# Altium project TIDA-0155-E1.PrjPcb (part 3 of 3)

## Sheet Page6.SchDoc
size 431 x 279 mm; Date: Not shown in title block; ApprovedBy: Not shown in title block; CheckedBy: Not shown in title block; Author: Not shown in title block; CompanyName: Not shown in title block; Engineer: Not shown in title block; Organization: Not shown in title block; Address1: Not shown in title block; Address2: Not shown in title block; Address3: Not shown in title block; Address4: Not shown in title block; DocumentNumber: 1; Revision: Use project parameter SCH_Rev; SheetNumber: 2; SheetTotal: 3; PageSetup: Record=PageOptions¦CenterHorizontal=True¦CenterVertical=True¦PrintScale=1.00¦XCorrection=1.00¦YCorrection=1.00¦PrintKind=0¦BorderSize=5000000¦LeftOffset=0¦BottomOffset=0¦Orientation=2¦PaperLength=1000¦PaperWidth=1000¦Scale=100¦PaperSource=15¦PrintQuality=600¦MediaType=1¦DitherType=10¦PaperKind=Letter¦PrintScaleMode=1
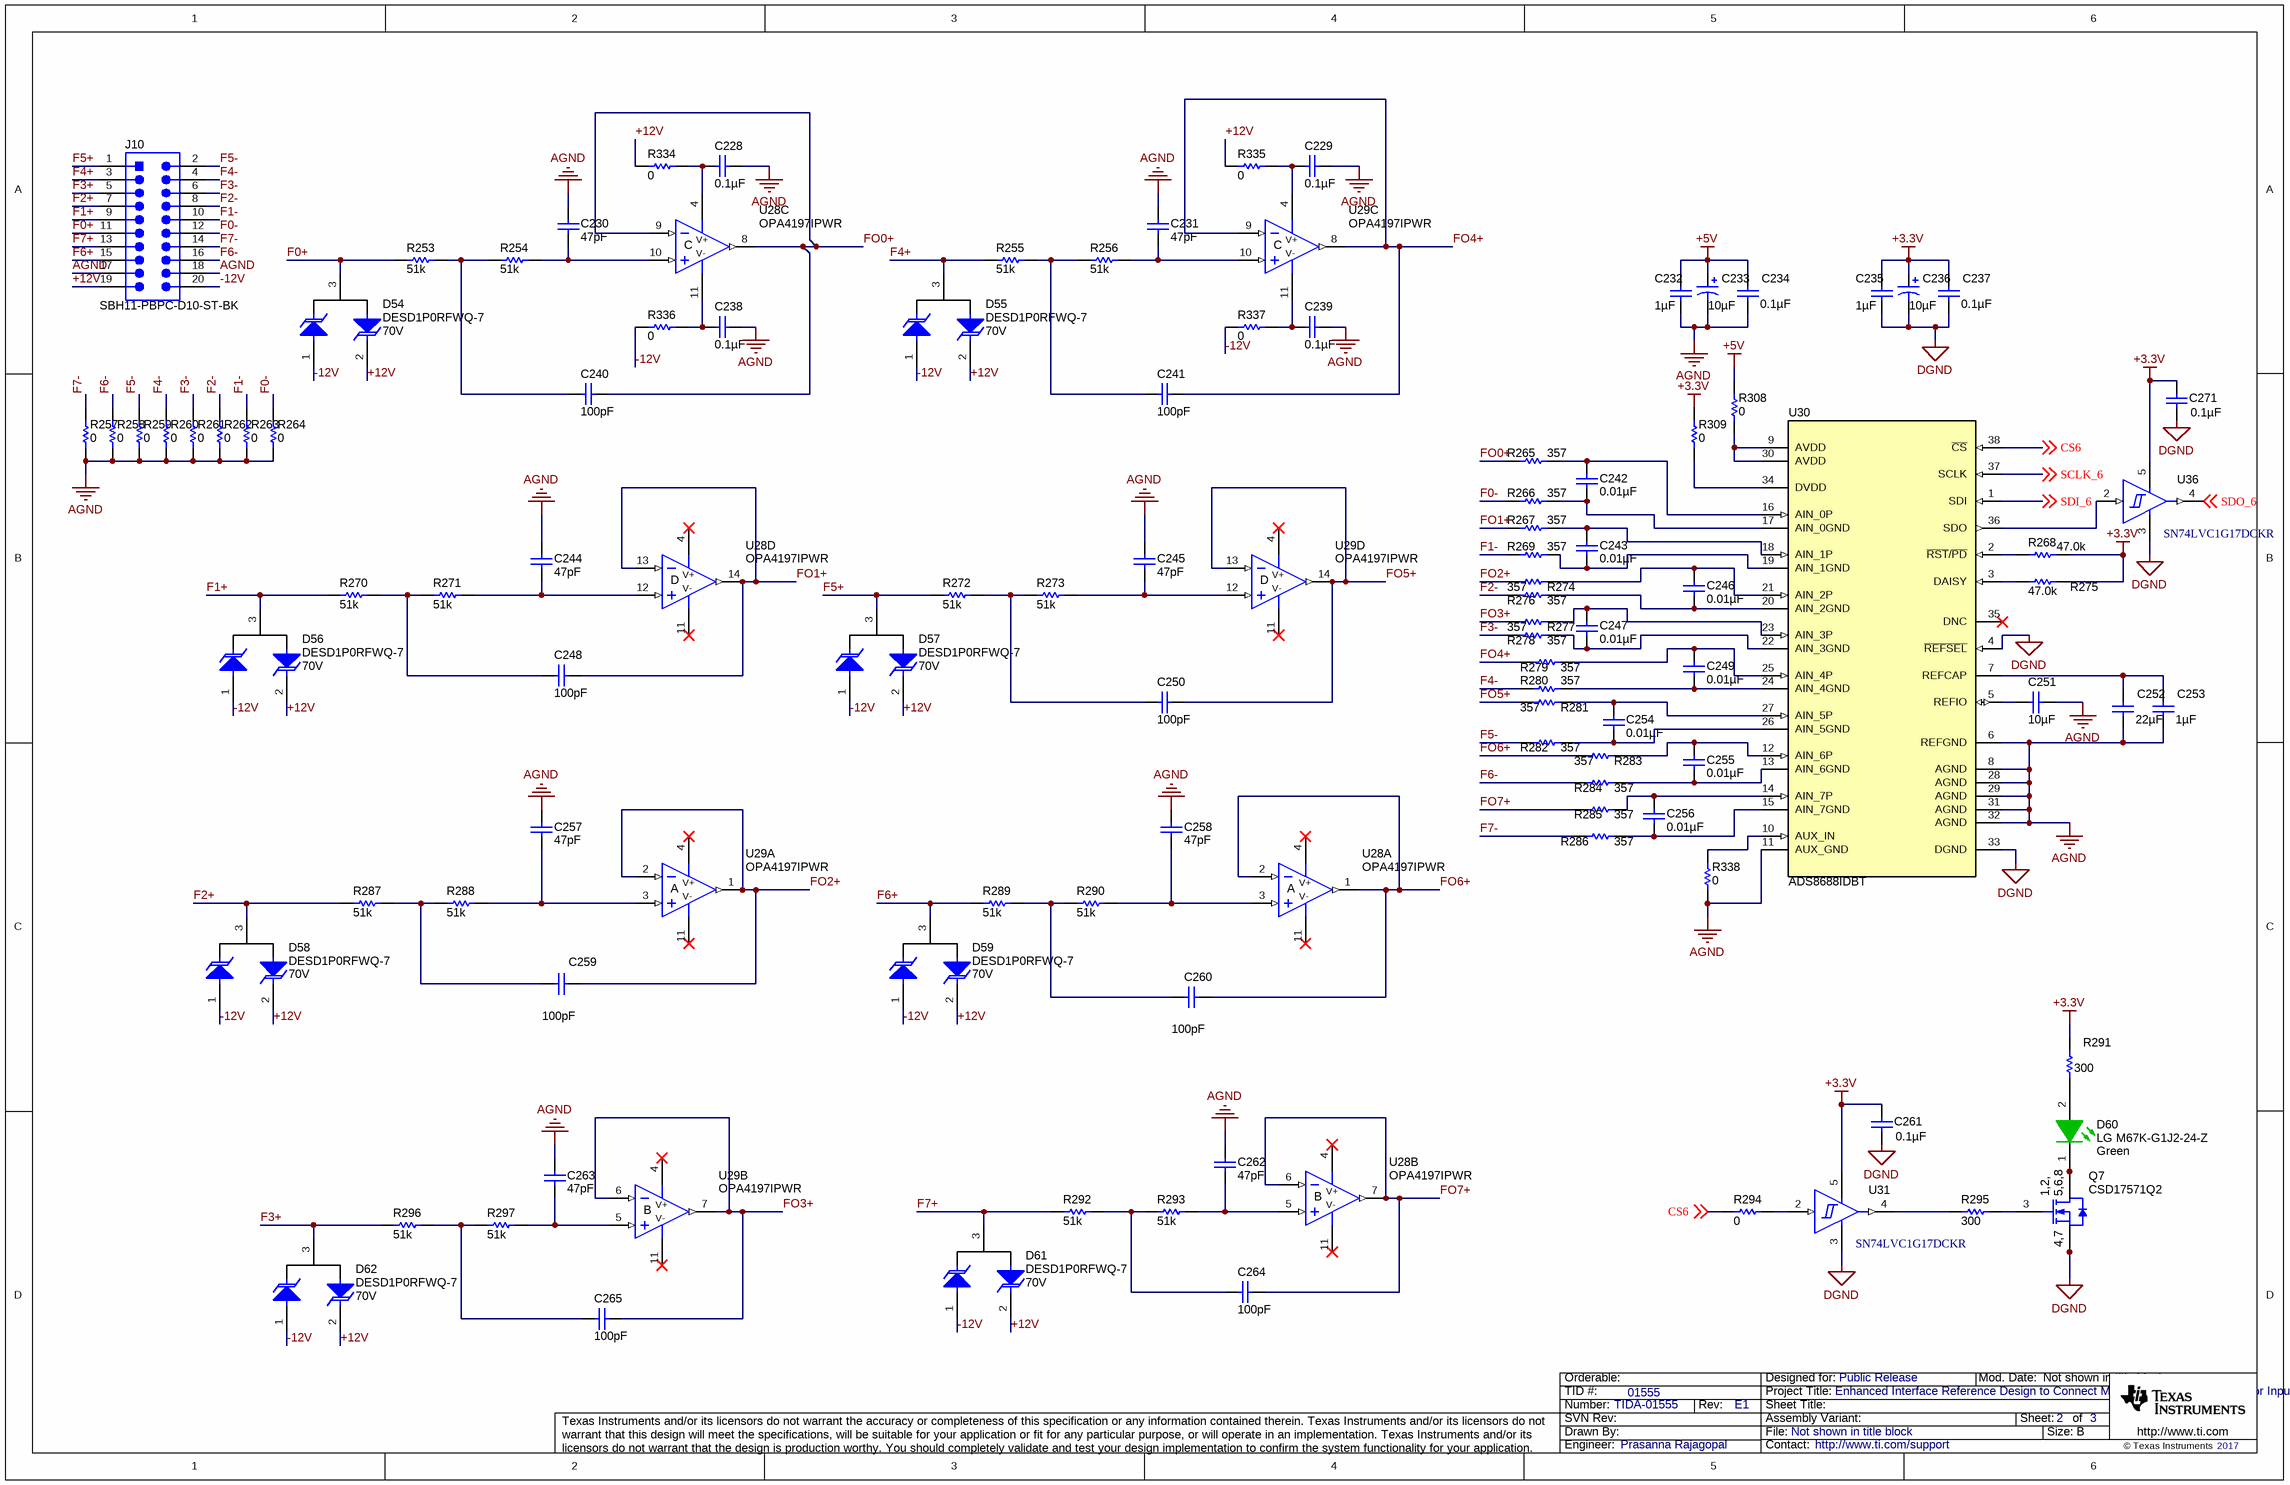
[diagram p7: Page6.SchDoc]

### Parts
C228  ValueDisplayed: 0.1µF  [0603]  (hidden comment: 06035C104KAT2A)
C229  ValueDisplayed: 0.1µF  [0603]  (hidden comment: 06035C104KAT2A)
C230  ValueDisplayed: 47pF  [0603]  (hidden comment: C0603C470J5GACTU)
C231  ValueDisplayed: 47pF  [0603]  (hidden comment: C0603C470J5GACTU)
C232  ValueDisplayed: 1µF  [0805_HV]  (hidden comment: LMK212B7105KD-T)
C233  ValueDisplayed: 10µF  [3216-18]  (hidden comment: TAJA106M010RNJ)
C234  ValueDisplayed: 0.1µF  [0402]  (hidden comment: C1005X5R1A104K050BA)
C235  ValueDisplayed: 1µF  [0805_HV]  (hidden comment: LMK212B7105KD-T)
C236  ValueDisplayed: 10µF  [3216-18]  (hidden comment: TAJA106M010RNJ)
C237  ValueDisplayed: 0.1µF  [0402]  (hidden comment: C1005X5R1A104K050BA)
C238  ValueDisplayed: 0.1µF  [0603]  (hidden comment: 06035C104KAT2A)
C239  ValueDisplayed: 0.1µF  [0603]  (hidden comment: 06035C104KAT2A)
C240  ValueDisplayed: 100pF  [0603]  (hidden comment: 06035A101FAT2A)
C241  ValueDisplayed: 100pF  [0603]  (hidden comment: 06035A101FAT2A)
C242  ValueDisplayed: 0.01µF  [0603]  (hidden comment: C1608X7R1H103K080AA)
C243  ValueDisplayed: 0.01µF  [0603]  (hidden comment: C1608X7R1H103K080AA)
C244  ValueDisplayed: 47pF  [0603]  (hidden comment: C0603C470J5GACTU)
C245  ValueDisplayed: 47pF  [0603]  (hidden comment: C0603C470J5GACTU)
C246  ValueDisplayed: 0.01µF  [0603]  (hidden comment: C1608X7R1H103K080AA)
C247  ValueDisplayed: 0.01µF  [0603]  (hidden comment: C1608X7R1H103K080AA)
C248  ValueDisplayed: 100pF  [0603]  (hidden comment: 06035A101FAT2A)
C249  ValueDisplayed: 0.01µF  [0603]  (hidden comment: C1608X7R1H103K080AA)
C250  ValueDisplayed: 100pF  [0603]  (hidden comment: 06035A101FAT2A)
C251  ValueDisplayed: 10µF  [0805_HV]  (hidden comment: GRM21BR71A106KE51L)
C252  ValueDisplayed: 22µF  [1210_280]  (hidden comment: C3225X7R1C226K250AC)
C253  ValueDisplayed: 1µF  [0603]  (hidden comment: C1608X7R1C105K080AC)
C254  ValueDisplayed: 0.01µF  [0603]  (hidden comment: C1608X7R1H103K080AA)
C255  ValueDisplayed: 0.01µF  [0603]  (hidden comment: C1608X7R1H103K080AA)
C256  ValueDisplayed: 0.01µF  [0603]  (hidden comment: C1608X7R1H103K080AA)
C257  ValueDisplayed: 47pF  [0603]  (hidden comment: C0603C470J5GACTU)
C258  ValueDisplayed: 47pF  [0603]  (hidden comment: C0603C470J5GACTU)
C259  ValueDisplayed: 100pF  [0603]  (hidden comment: 06035A101FAT2A)
C260  ValueDisplayed: 100pF  [0603]  (hidden comment: 06035A101FAT2A)
C261  ValueDisplayed: 0.1µF  [0603]  (hidden comment: GRM188R71C104KA01D)
C262  ValueDisplayed: 47pF  [0603]  (hidden comment: C0603C470J5GACTU)
C263  ValueDisplayed: 47pF  [0603]  (hidden comment: C0603C470J5GACTU)
C264  ValueDisplayed: 100pF  [0603]  (hidden comment: 06035A101FAT2A)
C265  ValueDisplayed: 100pF  [0603]  (hidden comment: 06035A101FAT2A)
C271  ValueDisplayed: 0.1µF  [0603]  (hidden comment: GRM188R71C104KA01D)
D54  DESD1P0RFWQ-7  value 70V  [SOT-323]
D55  DESD1P0RFWQ-7  value 70V  [SOT-323]
D56  DESD1P0RFWQ-7  value 70V  [SOT-323]
D57  DESD1P0RFWQ-7  value 70V  [SOT-323]
D58  DESD1P0RFWQ-7  value 70V  [SOT-323]
D59  DESD1P0RFWQ-7  value 70V  [SOT-323]
D60  LG M67K-G1J2-24-Z  value Green  [LG_M67K_Green]
D61  DESD1P0RFWQ-7  value 70V  [SOT-323]
D62  DESD1P0RFWQ-7  value 70V  [SOT-323]
J10  SBH11-PBPC-D10-ST-BK  [Sullins_SBH11-xxxC-D10-ST]
Q7  CSD17571Q2  [DQK0006C]
R253  ValueDisplayed: 51k  [0603]  (hidden comment: CRCW060351K0JNEA)
R254  ValueDisplayed: 51k  [0603]  (hidden comment: CRCW060351K0JNEA)
R255  ValueDisplayed: 51k  [0603]  (hidden comment: CRCW060351K0JNEA)
R256  ValueDisplayed: 51k  [0603]  (hidden comment: CRCW060351K0JNEA)
R257  ValueDisplayed: 0  [0603]  (hidden comment: CRCW06030000Z0EA)
R258  ValueDisplayed: 0  [0603]  (hidden comment: CRCW06030000Z0EA)
R259  ValueDisplayed: 0  [0603]  (hidden comment: CRCW06030000Z0EA)
R260  ValueDisplayed: 0  [0603]  (hidden comment: CRCW06030000Z0EA)
R261  ValueDisplayed: 0  [0603]  (hidden comment: CRCW06030000Z0EA)
R262  ValueDisplayed: 0  [0603]  (hidden comment: CRCW06030000Z0EA)
R263  ValueDisplayed: 0  [0603]  (hidden comment: CRCW06030000Z0EA)
R264  ValueDisplayed: 0  [0603]  (hidden comment: CRCW06030000Z0EA)
R265  ValueDisplayed: 357  [0402]  (hidden comment: CRCW0402357RFKED)
R266  ValueDisplayed: 357  [0402]  (hidden comment: CRCW0402357RFKED)
R267  ValueDisplayed: 357  [0402]  (hidden comment: CRCW0402357RFKED)
R268  ValueDisplayed: 47.0k  [0603]  (hidden comment: RC0603FR-0747KL)
R269  ValueDisplayed: 357  [0402]  (hidden comment: CRCW0402357RFKED)
R270  ValueDisplayed: 51k  [0603]  (hidden comment: CRCW060351K0JNEA)
R271  ValueDisplayed: 51k  [0603]  (hidden comment: CRCW060351K0JNEA)
R272  ValueDisplayed: 51k  [0603]  (hidden comment: CRCW060351K0JNEA)
R273  ValueDisplayed: 51k  [0603]  (hidden comment: CRCW060351K0JNEA)
R274  ValueDisplayed: 357  [0402]  (hidden comment: CRCW0402357RFKED)
R275  ValueDisplayed: 47.0k  [0603]  (hidden comment: RC0603FR-0747KL)
R276  ValueDisplayed: 357  [0402]  (hidden comment: CRCW0402357RFKED)
R277  ValueDisplayed: 357  [0402]  (hidden comment: CRCW0402357RFKED)
R278  ValueDisplayed: 357  [0402]  (hidden comment: CRCW0402357RFKED)
R279  ValueDisplayed: 357  [0402]  (hidden comment: CRCW0402357RFKED)
R280  ValueDisplayed: 357  [0402]  (hidden comment: CRCW0402357RFKED)
R281  ValueDisplayed: 357  [0402]  (hidden comment: CRCW0402357RFKED)
R282  ValueDisplayed: 357  [0402]  (hidden comment: CRCW0402357RFKED)
R283  ValueDisplayed: 357  [0402]  (hidden comment: CRCW0402357RFKED)
R284  ValueDisplayed: 357  [0402]  (hidden comment: CRCW0402357RFKED)
R285  ValueDisplayed: 357  [0402]  (hidden comment: CRCW0402357RFKED)
R286  ValueDisplayed: 357  [0402]  (hidden comment: CRCW0402357RFKED)
R287  ValueDisplayed: 51k  [0603]  (hidden comment: CRCW060351K0JNEA)
R288  ValueDisplayed: 51k  [0603]  (hidden comment: CRCW060351K0JNEA)
R289  ValueDisplayed: 51k  [0603]  (hidden comment: CRCW060351K0JNEA)
R290  ValueDisplayed: 51k  [0603]  (hidden comment: CRCW060351K0JNEA)
R291  ValueDisplayed: 300  [0603]  (hidden comment: CRCW0603300RJNEA)
R292  ValueDisplayed: 51k  [0603]  (hidden comment: CRCW060351K0JNEA)
R293  ValueDisplayed: 51k  [0603]  (hidden comment: CRCW060351K0JNEA)
R294  ValueDisplayed: 0  [0603]  (hidden comment: RMCF0603ZT0R00)
R295  ValueDisplayed: 300  [0603]  (hidden comment: CRCW0603300RJNEA)
R296  ValueDisplayed: 51k  [0603]  (hidden comment: CRCW060351K0JNEA)
R297  ValueDisplayed: 51k  [0603]  (hidden comment: CRCW060351K0JNEA)
R308  ValueDisplayed: 0  [0603]  (hidden comment: CRCW06030000Z0EA)
R309  ValueDisplayed: 0  [0603]  (hidden comment: CRCW06030000Z0EA)
R334  ValueDisplayed: 0  [0402]  (hidden comment: CRCW04020000Z0ED)
R335  ValueDisplayed: 0  [0402]  (hidden comment: CRCW04020000Z0ED)
R336  ValueDisplayed: 0  [0402]  (hidden comment: CRCW04020000Z0ED)
R337  ValueDisplayed: 0  [0402]  (hidden comment: CRCW04020000Z0ED)
R338  ValueDisplayed: 0  [0402]  (hidden comment: CRCW04020000Z0ED)
U28  OPA4197IPWR  [PW0014A_N]  (parts A,B,C,D of 4)
U29  OPA4197IPWR  [PW0014A_N]  (parts A,B,C,D of 4)
U30  ADS8688IDBT  [DBT0038A_N]
U31  SN74LVC1G17DCKR  [DCK0005A_N]
U36  SN74LVC1G17DCKR  [DCK0005A_N]

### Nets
+3.3V: C235.1 C236.1(+) C237.1 C261.1 C271.1 R268.2 R275.2 R291.2 R309.2 U31.5(VCC) U36.5(VCC)
+5V: C232.1 C233.1(+) C234.1 R308.2
+12V: D54.2(C) D55.2(C) D56.2(C) D57.2(C) D58.2(C) D59.2(C) D61.2(C) D62.2(C) J10.19 R334.1 R335.1
-12V: D54.1(A) D55.1(A) D56.1(A) D57.1(A) D58.1(A) D59.1(A) D61.1(A) D62.1(A) J10.20 R336.1 R337.1
AGND: C228.1 C229.1 C230.1 C231.1 C232.2 C233.2(-) C234.2 C238.1 C239.1 C244.1 C245.1 C251.2 C252.2 C253.2 C257.1 C258.1 C262.1 C263.1 J10.17 J10.18 R257.1 R258.1 R259.1 R260.1 R261.1 R262.1 R263.1 R264.1 R338.1 U30.6(REFGND) U30.8(AGND) U30.11(AUX_GND) U30.28(AGND) U30.29(AGND) U30.31(AGND) U30.32(AGND)
DGND: C235.2 C236.2(-) C237.2 C261.2 C271.2 Q7.4(S) Q7.7(S) U30.4(~{REFSEL}) U30.33(DGND) U31.3(GND) U36.3(GND)
CS6: R294.1 U30.38(~{CS}) ; off-sheet CS6
F0+: D54.3(C) J10.11 R253.1
F0-: J10.12 R264.2 R266.1
F1+: D56.3(C) J10.9 R270.1
F1-: J10.10 R263.2 R269.1
F2+: D58.3(C) J10.7 R287.1
F2-: J10.8 R262.2 R276.1
F3+: D62.3(C) J10.5 R296.1
F3-: J10.6 R261.2 R278.1
F4+: D55.3(C) J10.3 R255.1
F4-: J10.4 R260.2 R280.1
F5+: D57.3(C) J10.1 R272.1
F5-: J10.2 R259.2 R282.1
F6+: D59.3(C) J10.15 R289.1
F6-: J10.16 R258.2 R284.1
F7+: D61.3(C) J10.13 R292.1
F7-: J10.14 R257.2 R286.1
FO0+: C240.1 R265.1 U28.8(OUT) U28.9(IN-)
FO1+: C248.1 R267.1 U28.13(IN-) U28.14(OUT)
FO2+: C259.1 R274.1 U29.1(OUT) U29.2(IN-)
FO3+: C265.1 R277.1 U29.6(IN-) U29.7(OUT)
FO4+: C241.1 R279.1 U29.8(OUT) U29.9(IN-)
FO5+: C250.1 R281.1 U29.13(IN-) U29.14(OUT)
FO6+: C260.1 R283.1 U28.1(OUT) U28.2(IN-)
FO7+: C264.1 R285.1 U28.6(IN-) U28.7(OUT)
SCLK_6: U30.37(SCLK) ; off-sheet SCLK_6
SDI_6: U30.1(SDI) ; off-sheet SDI_6
SDO_6: U36.4(Y) ; off-sheet SDO_6
NetC228_2: C228.2 R334.2 U28.4(V+)
NetC229_2: C229.2 R335.2 U29.4(V+)
NetC230_2: C230.2 R254.2 U28.10(IN+)
NetC231_2: C231.2 R256.2 U29.10(IN+)
NetC238_2: C238.2 R336.2 U28.11(V-)
NetC239_2: C239.2 R337.2 U29.11(V-)
NetC240_2: C240.2 R253.2 R254.1
NetC241_2: C241.2 R255.2 R256.1
NetC242_1: C242.1 R265.2 U30.16(AIN_0P)
NetC242_2: C242.2 R266.2 U30.17(AIN_0GND)
NetC243_1: C243.1 R267.2 U30.18(AIN_1P)
NetC243_2: C243.2 R269.2 U30.19(AIN_1GND)
NetC244_2: C244.2 R271.2 U28.12(IN+)
NetC245_2: C245.2 R273.2 U29.12(IN+)
NetC246_1: C246.1 R274.2 U30.21(AIN_2P)
NetC246_2: C246.2 R276.2 U30.20(AIN_2GND)
NetC247_1: C247.1 R277.2 U30.23(AIN_3P)
NetC247_2: C247.2 R278.2 U30.22(AIN_3GND)
NetC248_2: C248.2 R270.2 R271.1
NetC249_1: C249.1 R279.2 U30.25(AIN_4P)
NetC249_2: C249.2 R280.2 U30.24(AIN_4GND)
NetC250_2: C250.2 R272.2 R273.1
NetC251_1: C251.1 U30.5(REFIO)
NetC252_1: C252.1 C253.1 U30.7(REFCAP)
NetC254_1: C254.1 R281.2 U30.27(AIN_5P)
NetC254_2: C254.2 R282.2 U30.26(AIN_5GND)
NetC255_1: C255.1 R283.2 U30.12(AIN_6P)
NetC255_2: C255.2 R284.2 U30.13(AIN_6GND)
NetC256_1: C256.1 R285.2 U30.14(AIN_7P)
NetC256_2: C256.2 R286.2 U30.15(AIN_7GND)
NetC257_2: C257.2 R288.2 U29.3(IN+)
NetC258_2: C258.2 R290.2 U28.3(IN+)
NetC259_2: C259.2 R287.2 R288.1
NetC260_2: C260.2 R289.2 R290.1
NetC262_2: C262.2 R293.2 U28.5(IN+)
NetC263_2: C263.2 R297.2 U29.5(IN+)
NetC264_2: C264.2 R292.2 R293.1
NetC265_2: C265.2 R296.2 R297.1
NetD60_1: D60.1(K) Q7.1(D) Q7.2(D) Q7.5(D) Q7.6(D) Q7.8(D)
NetD60_2: D60.2(A) R291.1
NetQ7_3: Q7.3(G) R295.1
NetR268_1: R268.1 U30.2(~{RST}/~{PD})
NetR275_1: R275.1 U30.3(DAISY)
NetR294_2: R294.2 U31.2(A)
NetR295_2: R295.2 U31.4(Y)
NetR308_1: R308.1 U30.9(AVDD) U30.30(AVDD)
NetR309_1: R309.1 U30.34(DVDD)
NetR338_2: R338.2 U30.10(AUX_IN)
NetU30_36: U30.36(SDO) U36.2(A)

Not connected (* = marked no-connect by the designer): U30 35(DNC)*

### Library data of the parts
C228 C229 C238 C239 = 06035C104KAT2A: CAP, CERM, 0.1 µF, 50 V,+/- 10%, X7R, 0603; Manufacturer: AVX; Polarized: N; CompType: Capacitor; Value: 0.1uF; U/M: EA; Cap_F: 0.0000001; Tolerance_%: 10; VDC_V: 50; Value2: 50V; TaMin_C: -55; TaMax_C: 125; SizeArea_mm2: 1.28; SizeAreaWB_mm2: 4.68; SizeX_mm: 1.6; SizeY_mm: 0.8; SizeZ_mm: 1; AEC Category: Q200; Green_Lifecycle: Active; Green_REACh: Passed
C230 C231 C244 C245 C257 C258 C262 C263 = C0603C470J5GACTU: CAP, CERM, 47 pF, 50 V,+/- 5%, C0G/NP0, 0603; Manufacturer: Kemet; Polarized: N; CompType: Capacitor; Value: 47pF; U/M: EA; Cap_F: 0.000000000047; Tolerance_%: 5; VDC_V: 50; Value2: 50V; TaMin_C: -55; TaMax_C: 125; SizeArea_mm2: 1.28; SizeAreaWB_mm2: 4.68; SizeX_mm: 1.6; SizeY_mm: 0.8; SizeZ_mm: 1; AEC Category: Q200; Green_Lifecycle: Active; Green_REACh: Passed
C232 C235 = LMK212B7105KD-T: CAP, CERM, 1 µF, 10 V, +/- 10%, X7R, 0805; Manufacturer: Taiyo Yuden; Polarized: N; CompType: Capacitor; Value: 1uF; U/M: EA; Cap_F: 0.000001; Tolerance_%: 10; Value1: Unknown; Value2: 10V; TaMin_C: -55; TaMax_C: 125; Cap_Case: 0805; SizeArea_mm2: 2.5; SizeAreaWB_mm2: 6.75; SizeX_mm: 2; SizeY_mm: 1.25; SizeZ_mm: 1.45; AEC Category: Q200
C233 C236 = TAJA106M010RNJ: CAP, TA, 10 µF, 10 V, +/- 20%, 3 ohm, SMD; Manufacturer: AVX; Polarized: Y; CompType: Capacitor; Value: 10uF; U/M: EA; Cap_F: 0.00001; Tolerance_%: 20; Value1: 3 ohm; VDC_V: 10; Value2: 10V; ESR_ohm: 3; TaMin_C: -55; TaMax_C: 125; SizeAreaWB_mm2: 10.92; SizeArea_mm2: 5.12; SizeX_mm: 3.2; SizeY_mm: 1.6; SizeZ_mm: 1.8; AEC Category: Q200
C234 C237 = C1005X5R1A104K050BA: CAP, CERM, 0.1 µF, 10 V, +/- 10%, X5R, 0402; Manufacturer: TDK; Polarized: N; CompType: Capacitor; Value: 0.1uF; U/M: EA; Cap_F: 0.0000001; Tolerance_%: 10; Value1: Unknown; Value2: 10V; TaMin_C: -55; TaMax_C: 85; SizeArea_mm2: 0.5; SizeAreaWB_mm2: 3; SizeX_mm: 1; SizeZ_mm: 0.6; AEC Category: Q200
C240 C241 C248 C250 C259 C260 C264 C265 = 06035A101FAT2A: CAP, CERM, 100 pF, 50 V,+/- 1%, C0G/NP0, 0603; Manufacturer: AVX; Polarized: N; CompType: Capacitor; Value: 100pF; U/M: EA; Cap_F: 0.0000000001; Tolerance_%: 1; VDC_V: 50; Value2: 50V; TaMin_C: -55; TaMax_C: 125; SizeArea_mm2: 1.28; SizeAreaWB_mm2: 4.68; SizeX_mm: 1.6; SizeY_mm: 0.8; AEC Category: Q200; Green_Lifecycle: Active; Green_REACh: Passed
C242 C243 C246 C247 C249 C254-C256 = C1608X7R1H103K080AA: CAP, CERM, 0.01 µF, 50 V,+/- 10%, X7R, 0603; Manufacturer: TDK; Polarized: N; CompType: Capacitor; Value: 0.01uF; U/M: EA; Cap_F: 0.00000001; Tolerance_%: 10; ESR_ohm: 0.0539; Value1: 0.0539 ohm; VDC_V: 50; Value2: 50V; TaMin_C: -55; TaMax_C: 125; SizeArea_mm2: 1.28; SizeAreaWB_mm2: 4.68; SizeX_mm: 1.6; SizeY_mm: 0.8; SizeZ_mm: 1; AEC Category: Q200; Green_Lifecycle: NRND; Green_REACh: Passed
C251 = GRM21BR71A106KE51L: CAP, CERM, 10 µF, 10 V,+/- 10%, X7R, 0805; Manufacturer: MuRata; Polarized: N; CompType: Capacitor; Value: 10uF; U/M: EA; Cap_F: 0.00001; Tolerance_%: 10; ESR_ohm: 0.003; Value1: 0.003 ohm; Value2: 10V; TaMin_C: -55; TaMax_C: 125; Cap_Case: 0805; SizeArea_mm2: 2.5; SizeAreaWB_mm2: 6.75; SizeX_mm: 2; SizeY_mm: 1.25; SizeZ_mm: 1.45; AEC Category: Q200; Green_Lifecycle: Active; Green_REACh: Passed
C252 = C3225X7R1C226K250AC: CAP, CERM, 22 µF, 16 V,+/- 10%, X7R, 1210; Manufacturer: TDK; Polarized: N; CompType: Capacitor; Value: 22uF; U/M: EA; Cap_F: 0.000022; Tolerance_%: 10; ESR_ohm: 0.002582; Value1: 0.002582 ohm; VDC_V: 16; Value2: 16V; IRMS_A: 4.57562; TaMin_C: -55; TaMax_C: 125; Cap_Case: 1210; SizeArea_mm2: 8; SizeAreaWB_mm2: 14.7; SizeX_mm: 3.2; SizeY_mm: 2.5; SizeZ_mm: 2.8; AEC Category: Q200; Green_Lifecycle: Active; Green_REACh: Passed
C253 = C1608X7R1C105K080AC: CAP, CERM, 1 µF, 16 V,+/- 10%, X7R, 0603; Manufacturer: TDK; Polarized: N; CompType: Capacitor; Value: 1uF; U/M: EA; Cap_F: 0.000001; Tolerance_%: 10; ESR_ohm: 0.0057; Value1: 0.0057 ohm; VDC_V: 16; Value2: 16V; TaMin_C: -55; TaMax_C: 125; SizeArea_mm2: 1.28; SizeAreaWB_mm2: 4.68; SizeX_mm: 1.6; SizeY_mm: 0.8; SizeZ_mm: 1; AEC Category: Q200; Green_Lifecycle: Active; Green_REACh: Passed
C261 C271 = GRM188R71C104KA01D: CAP, CERM, 0.1 µF, 16 V, +/- 10%, X7R, 0603; Manufacturer: MuRata; Polarized: N; CompType: Capacitor; Value: 0.1uF; U/M: EA; Cap_F: 0.0000001; Tolerance_%: 10; Value1: Unknown; VDC_V: 16; Value2: 16V; TaMin_C: -55; TaMax_C: 125; SizeArea_mm2: 1.28; SizeAreaWB_mm2: 4.68; SizeX_mm: 1.6; SizeY_mm: 0.8; SizeZ_mm: 1; AEC Category: Q200
D54-D59 D61 D62 = DESD1P0RFWQ-7: Diode, TVS, Uni, 70 V, SOT-323; Manufacturer: Diodes Inc.; SymbolCreator: x0208325; U/M: EA; Power_W: 0.2; Vr_V: 70; Value1: 0.2W; SizeAreaWB_mm2: 10.24; SizeArea_mm2: 4.84; SizeX_mm: 2.2; SizeZ_mm: 1.1; AEC Category: Q101
D60 = LG M67K-G1J2-24-Z: LED, Green, SMD; Manufacturer: OSRAM; SymbolCreator: Altium; Type: AlInGaP; Vf_V: 1.8; Value2: 1.8V; Io_A: 0.002; Vr_V: 12; Tjmax_C: 125; Value1: W; Angle: 120; U/M: EA
J10 = SBH11-PBPC-D10-ST-BK: Header (Shrouded), 2.54mm, 10x2, Gold, Black, TH; Manufacturer: Sullins Connector Solutions; SymbolCreator: a0412235; Pitch_mm: 2.54; Gender: Male; Shrouded: Y; Row_Count: 2; Current_A: 3; Voltage_V: 1000; Green_Lifecycle: Not Set; Green_REACh: Incomplete
Q7 = CSD17571Q2: MOSFET, N-CH, 30 V, 22 A, DQK0006C (WSON-6); Manufacturer: Texas Instruments; Alternate Manufacturer: None; U/M: EA; ChType: N; Value: 30V; VdsMax_V: 30; Value1: 0.029 ohm; Rdson45_ohm: 0.029; Value2: 2.4 nC; QgTyp_nC: 2.4; Vgs_V: 20; IdsMax_A: 22; SizeAreaWB_mm2: 9; SizeArea_mm2: 4; SizeX_mm: 2; SizeZ_mm: 0.8; AEC Category: Q101
R253-R256 R270-R273 R287-R290 R292 R293 R296 R297 = CRCW060351K0JNEA: RES, 51 k, 5%, 0.1 W, 0603; Manufacturer: Vishay-Dale; CompType: Resistor; Value: 51k; Res_ohm: 51000; Value_Code: 51k0; Tolerance_%: 5; Power_W: 0.1; Value2: 0.1W; VDC_V: 75; TempCo: 200 ppm/C; SizeArea_mm2: 1.28; SizeX_mm: 1.6; SizeY_mm: 0.8; SizeZ_mm: 1; EIA_Code: E24; U/M: EA; AEC Category: Q200; Green_Lifecycle: Active; Green_REACh: Passed
R257-R264 R308 R309 = CRCW06030000Z0EA: RES, 0, 5%, 0.1 W, 0603; Manufacturer: Vishay-Dale; CompType: Resistor; Value: 0; Value_Code: 0000; Tolerance_%: 5; Power_W: 0.1; Value2: 0.1W; VDC_V: 75; TempCo: 200 ppm/C; EIA_Code: E24; U/M: EA
R265-R267 R269 R274 R276-R286 = CRCW0402357RFKED: RES, 357, 1%, 0.063 W, 0402; Manufacturer: Vishay-Dale; CompType: Resistor; Value: 357; Value_Code: 357R; Tolerance_%: 1; Power_W: 0.063; Value2: 0.063W; VDC_V: 50; TempCo: 100 ppm/C; SizeArea_mm2: 0.5; SizeZ_mm: 0.6; EIA_Code: E96; U/M: EA; AEC Category: Q200; Green_Lifecycle: Active; Green_REACh: Passed
R268 R275 = RC0603FR-0747KL: RES, 47.0 k, 1%, 0.1 W, 0603; Manufacturer: Yageo America; CompType: Resistor; Value: 47.0k; Res_ohm: 47000; Value_Code: 47k0; Tolerance_%: 1; Power_W: 0.1; Value2: 0.1W; VDC_V: 150; TempCo: 200 ppm/C; SizeArea_mm2: 1.28; SizeX_mm: 1.6; SizeY_mm: 0.8; U/M: EA; AEC Category: Q200; Green_Lifecycle: Active; Green_REACh: Passed
R291 R295 = CRCW0603300RJNEA: RES, 300, 5%, 0.1 W, 0603; Manufacturer: Vishay-Dale; CompType: Resistor; Value: 300; Value_Code: 300R; Tolerance_%: 5; Power_W: 0.1; Value2: 0.1W; VDC_V: 75; TempCo: 200 ppm/C; SizeArea_mm2: 1.28; SizeX_mm: 1.6; SizeY_mm: 0.8; SizeZ_mm: 1; EIA_Code: E24; U/M: EA; AEC Category: Q200
R294 = RMCF0603ZT0R00: RES, 0, 1%, 0.1 W, AEC-Q200 Grade 0, 0603; Manufacturer: Stackpole Electronics Inc; CompType: Resistor; Value: 0; Tolerance_%: 1; Power_W: 0.1; Value2: 0.1W; TempCo: ppm/C; SizeArea_mm2: 1.28; SizeX_mm: 1.6; SizeY_mm: 0.8; U/M: EA; AEC Category: Q200; AEC Qualified: Y
R334-R338 = CRCW04020000Z0ED: RES, 0, 5%, 0.063 W, 0402; Manufacturer: Vishay-Dale; CompType: Resistor; Value: 0; Value_Code: 0000; Tolerance_%: 5; Power_W: 0.063; Value2: 0.063W; VDC_V: 50; TempCo: 200 ppm/C; EIA_Code: E24; U/M: EA; SizeArea_mm2: 0.5; SizeX_mm: 1; SizeZ_mm: 0.6; AEC Category: Q200; Green_Lifecycle: Active; Green_REACh: Passed
U28 U29 = OPA4197IPWR: 36-V, Precision, Rail-to-Rail Input Output, Low Offset Voltage Op Amp, PW0014A (TSSOP-14); Manufacturer: Texas Instruments; SymbolCreator: a0412235; SizeArea_mm2: 32; SizeAreaWB_mm2: 58.8; SizeX_mm: 6.4; SizeY_mm: 5; SizeZ_mm: 1.2; CompType: IC; U/M: EA
U30 = ADS8688IDBT: 16-Bit, 500-kSPS, 8-Channel, Single-Supply, SAR ADCs with Bipolar Input Ranges, DBT0038A (TSSOP-38); Manufacturer: Texas Instruments; SymbolCreator: Altium; SizeArea_mm2: 62.08; SizeAreaWB_mm2: 98.28; SizeX_mm: 6.4; SizeY_mm: 9.7; SizeZ_mm: 1.2; CompType: IC; U/M: EA
U31 U36 = SN74LVC1G17DCKR: SINGLE SCHMITT-TRIGGER BUFFER, DCK0005A (SOT-SC70-5); Alternate PartNumber: SN74LVC1G17DCKT; Manufacturer: Texas Instruments; SymbolCreator: a0799628; SizeArea_mm2: 4.2; SizeAreaWB_mm2: 9.3; SizeX_mm: 2.1; SizeY_mm: 2; SizeZ_mm: 1.1; CompType: IC; U/M: EA

## Sheet Paget2.SchDoc
size 431 x 279 mm; Date: Not shown in title block; ApprovedBy: Not shown in title block; CheckedBy: Not shown in title block; Author: Not shown in title block; CompanyName: Not shown in title block; Engineer: Not shown in title block; Organization: Not shown in title block; Address1: Not shown in title block; Address2: Not shown in title block; Address3: Not shown in title block; Address4: Not shown in title block; DocumentNumber: 1; Revision: Use project parameter SCH_Rev; SheetNumber: 2; SheetTotal: 3; PageSetup: Record=PageOptions¦CenterHorizontal=True¦CenterVertical=True¦PrintScale=1.00¦XCorrection=1.00¦YCorrection=1.00¦PrintKind=0¦BorderSize=5000000¦LeftOffset=0¦BottomOffset=0¦Orientation=2¦PaperLength=1000¦PaperWidth=1000¦Scale=100¦PaperSource=15¦PrintQuality=600¦MediaType=1¦DitherType=10¦PaperKind=Letter¦PrintScaleMode=1
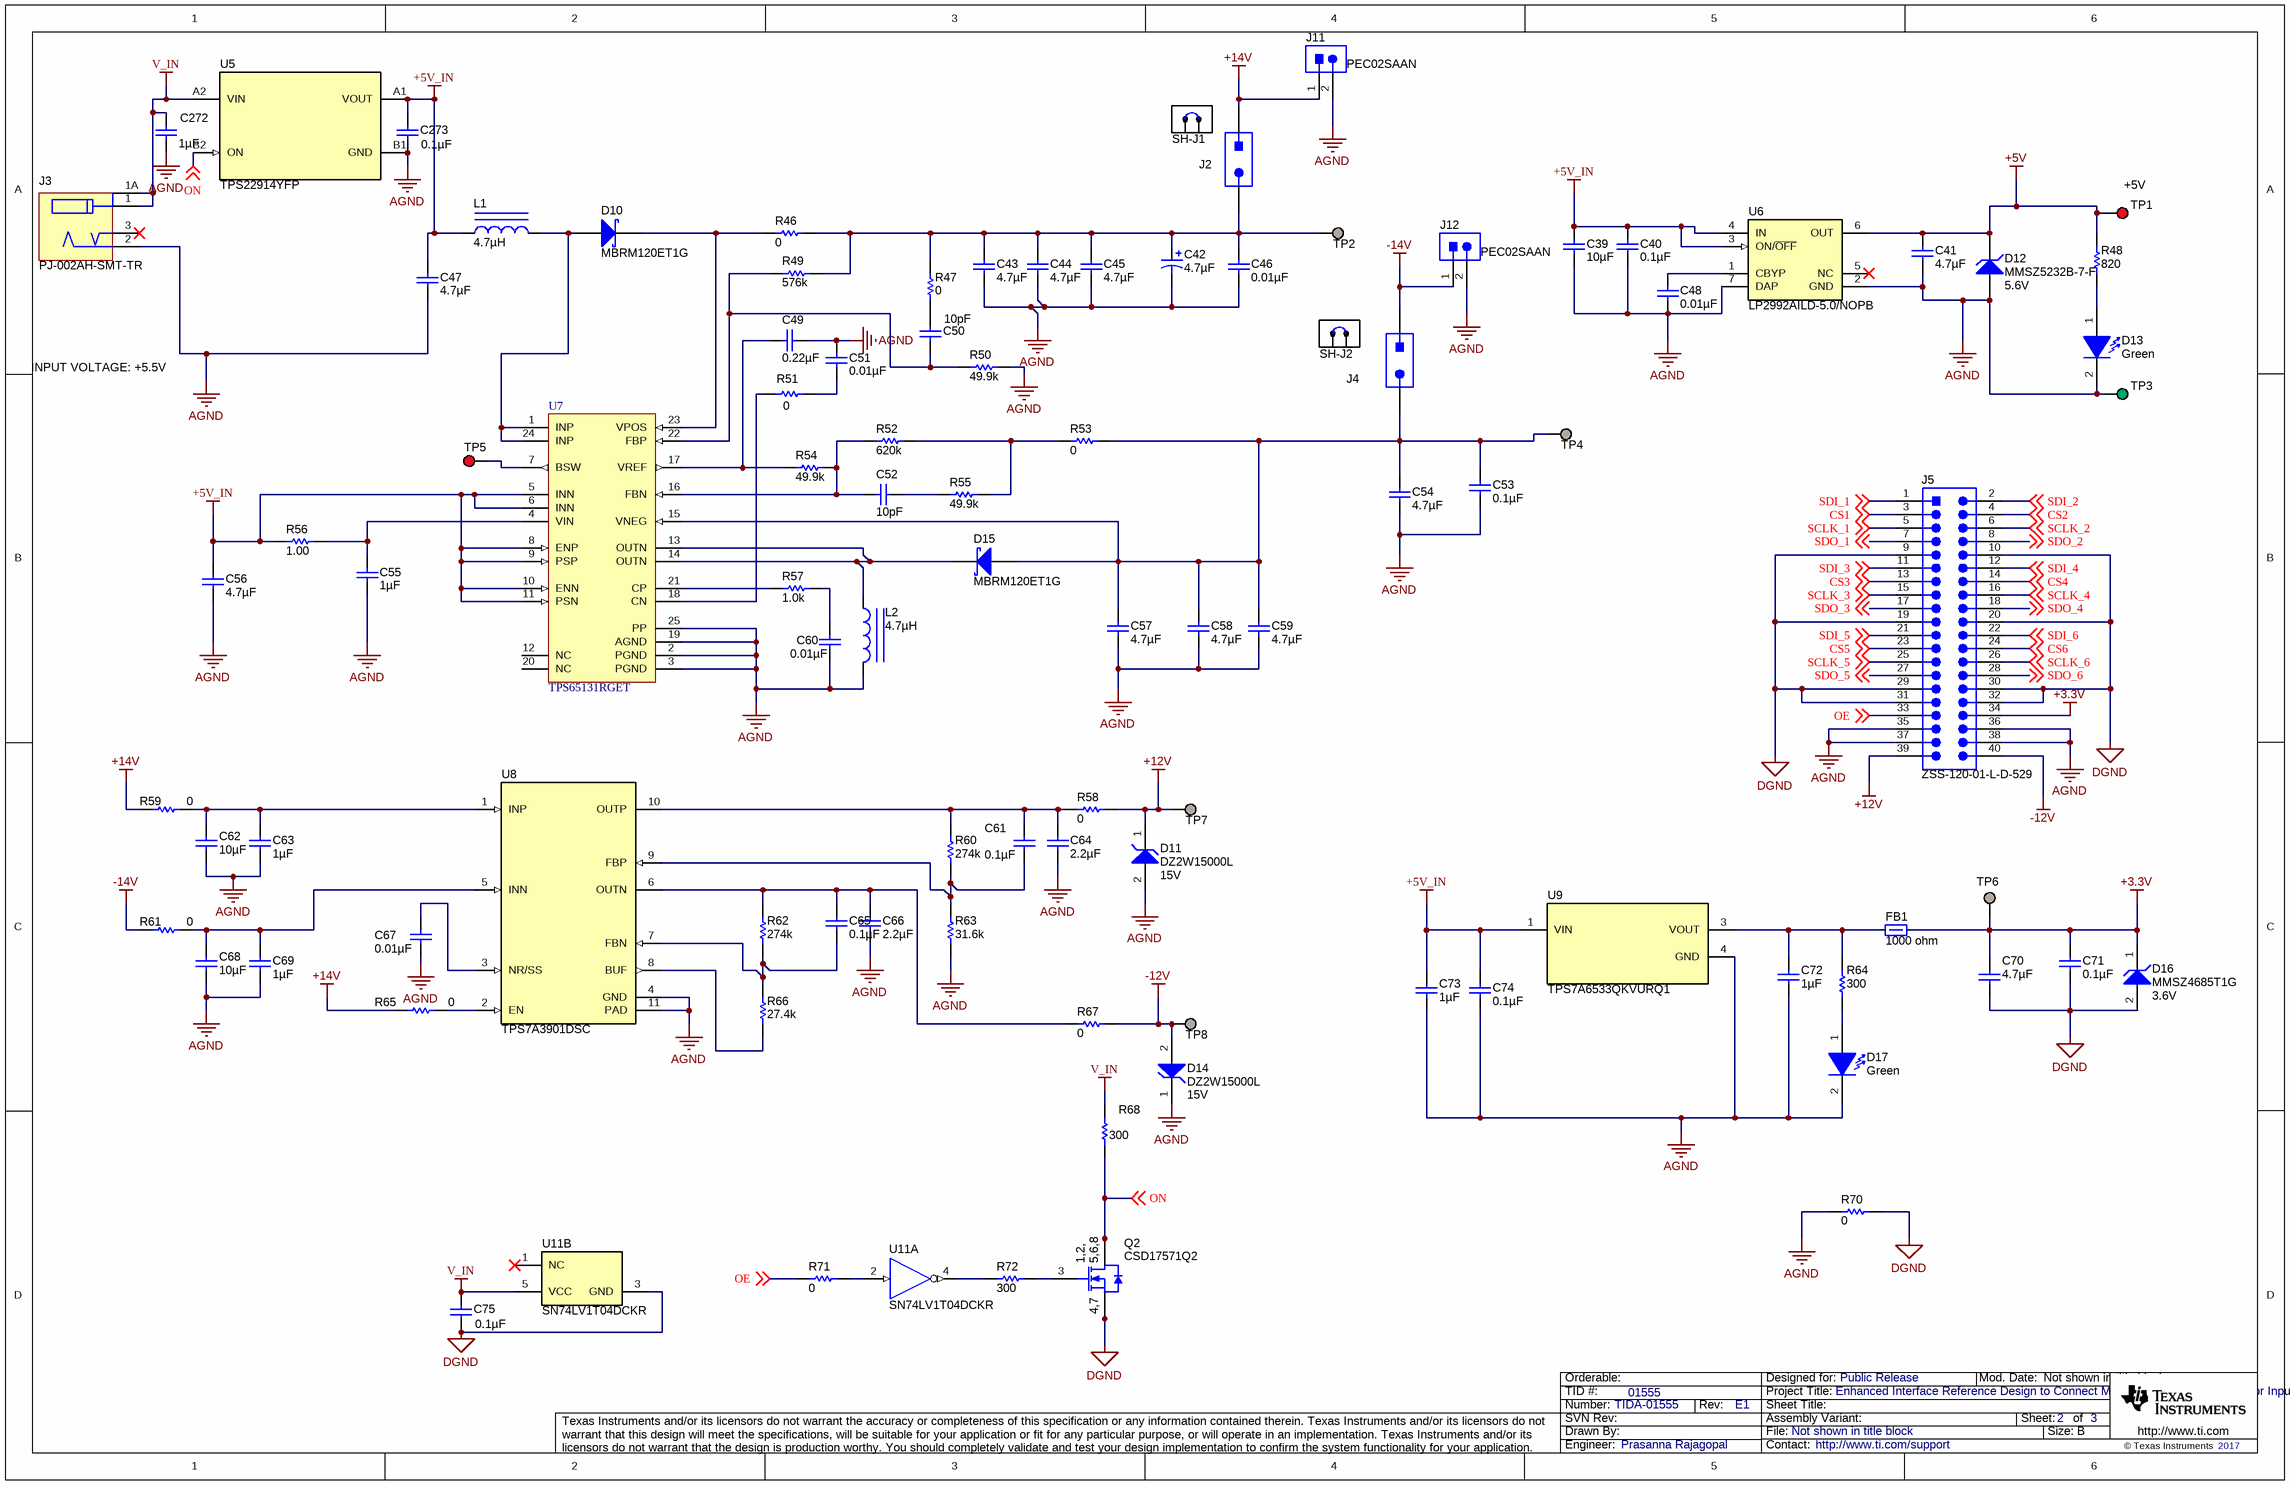
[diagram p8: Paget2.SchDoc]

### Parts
C39  ValueDisplayed: 10µF  [1206]  (hidden comment: 885012208069)
C40  ValueDisplayed: 0.1µF  [0603]  (hidden comment: 06033C104JAT2A)
C41  ValueDisplayed: 4.7µF  [1206]  (hidden comment: C3216X7R1E475M160AC)
C42  ValueDisplayed: 4.7µF  [6032-28]  (hidden comment: 293D475X9025C2TE3)
C43  ValueDisplayed: 4.7µF  [1206]  (hidden comment: C3216X7R1E475M160AC)
C44  ValueDisplayed: 4.7µF  [1206]  (hidden comment: C3216X7R1E475M160AC)
C45  ValueDisplayed: 4.7µF  [1206]  (hidden comment: C3216X7R1E475M160AC)
C46  ValueDisplayed: 0.01µF  [0603]  (hidden comment: GRM188R70J103KA01D)
C47  ValueDisplayed: 4.7µF  [1206]  (hidden comment: C3216X7R1E475M160AC)
C48  ValueDisplayed: 0.01µF  [0603]  (hidden comment: C1608X7R1H103K080AA)
C49  ValueDisplayed: 0.22µF  [0603]  (hidden comment: C0603C224K9RACTU)
C50  ValueDisplayed: 10pF  [0603]  (hidden comment: C0603C100J5GACTU)
C51  ValueDisplayed: 0.01µF  [0603]  (hidden comment: GRM188R70J103KA01D)
C52  ValueDisplayed: 10pF  [0603]  (hidden comment: C0603C100J5GACTU)
C53  ValueDisplayed: 0.1µF  [0603]  (hidden comment: 06033C104JAT2A)
C54  ValueDisplayed: 4.7µF  [1206]  (hidden comment: C3216X7R1E475M160AC)
C55  ValueDisplayed: 1µF  [0603]  (hidden comment: GRM188R61E105KA12D)
C56  ValueDisplayed: 4.7µF  [1206]  (hidden comment: C3216X7R1E475M160AC)
C57  ValueDisplayed: 4.7µF  [1206]  (hidden comment: C3216X7R1E475M160AC)
C58  ValueDisplayed: 4.7µF  [1206]  (hidden comment: C3216X7R1E475M160AC)
C59  ValueDisplayed: 4.7µF  [1206]  (hidden comment: C3216X7R1E475M160AC)
C60  ValueDisplayed: 0.01µF  [0603]  (hidden comment: GRM188R70J103KA01D)
C61  ValueDisplayed: 0.1µF  [0603]  (hidden comment: 06033C104JAT2A)
C62  ValueDisplayed: 10µF  [1210]
C63  ValueDisplayed: 1µF  [0603]  (hidden comment: GRM188R61E105KA12D)
C64  ValueDisplayed: 2.2µF  [0805_HV]  (hidden comment: C0805C225K8RACTU)
C65  ValueDisplayed: 0.1µF  [0603]  (hidden comment: 06033C104JAT2A)
C66  ValueDisplayed: 2.2µF  [0805_HV]  (hidden comment: C0805C225K8RACTU)
C67  ValueDisplayed: 0.01µF  [0603]  (hidden comment: GRM188R70J103KA01D)
C68  ValueDisplayed: 10µF  [1210]
C69  ValueDisplayed: 1µF  [0603]  (hidden comment: GRM188R61E105KA12D)
C70  ValueDisplayed: 4.7µF  [0805_HV]  (hidden comment: C2012X5R1H475M125AB)
C71  ValueDisplayed: 0.1µF  [0603]  (hidden comment: C0603C104K5RACTU)
C72  ValueDisplayed: 1µF  [0603]  (hidden comment: CGA3E3X5R1H105K080AB)
C73  ValueDisplayed: 1µF  [0603]  (hidden comment: CGA3E3X5R1H105K080AB)
C74  ValueDisplayed: 0.1µF  [0603]  (hidden comment: C0603C104K5RACTU)
C75  ValueDisplayed: 0.1µF  [0603]  (hidden comment: GRM188R71C104KA01D)
C272  ValueDisplayed: 1µF  [0603]  (hidden comment: C1608X7R1C105K080AC)
C273  ValueDisplayed: 0.1µF  [0603]  (hidden comment: GRM188R71C104KA01D)
D10  MBRM120ET1G  [POWERMITE]
D11  DZ2W15000L  value 15V  [SOD-123]
D12  MMSZ5232B-7-F  value 5.6V  [SOD-123]
D13  value Green  [LG L29K_GREEN]  (hidden comment: LG L29K-G2J1-24-Z)
D14  DZ2W15000L  value 15V  [SOD-123]
D15  MBRM120ET1G  [POWERMITE]
D16  MMSZ4685T1G  value 3.6V  [SOD-123]
D17  value Green  [LG L29K_GREEN]  (hidden comment: LG L29K-G2J1-24-Z)
FB1  value 1000 ohm  [MMZ1608_095]  (hidden comment: MMZ1608B102CTA00)
J2  5-146280-2  [TSW-102-07-G-S]  (value not drawn)
J3  PJ-002AH-SMT-TR  [CUI_PJ-002AH-SMT]
J4  5-146280-2  [TSW-102-07-G-S]  (value not drawn)
J5  ZSS-120-01-L-D-529  [CONN_ZSS-120-01-L-D-529]
J11  PEC02SAAN  [CONN_PEC02SAAN]
J12  PEC02SAAN  [CONN_PEC02SAAN]
L1  ValueDisplayed: 4.7µH  [VLF504012MT]  (hidden comment: VLF504012MT-4R7M)
L2  ValueDisplayed: 4.7µH  [VLF504012MT]  (hidden comment: VLF504012MT-4R7M)
Q2  CSD17571Q2  [DQK0006C]
R46  value 0  [1206]  (hidden comment: CRCW12060000Z0EA)
R47  ValueDisplayed: 0  [0603]  (hidden comment: CRCW06030000Z0EA)
R48  ValueDisplayed: 820  [0603]  (hidden comment: RC0603FR-07820RL)
R49  ValueDisplayed: 576k  [0603]  (hidden comment: CRCW0603576KFKEA)
R50  ValueDisplayed: 49.9k  [0603]  (hidden comment: RG1608P-4992-B-T5)
R51  ValueDisplayed: 0  [0603]  (hidden comment: CRCW06030000Z0EA)
R52  ValueDisplayed: 620k  [0603]  (hidden comment: CRCW0603620KFKEA)
R53  ValueDisplayed: 0  [0603]  (hidden comment: CRCW06030000Z0EA)
R54  ValueDisplayed: 49.9k  [0603]  (hidden comment: RG1608P-4992-B-T5)
R55  ValueDisplayed: 49.9k  [0603]  (hidden comment: RG1608P-4992-B-T5)
R56  ValueDisplayed: 1.00  [0603]  (hidden comment: CR0603-J/-1R0ELF)
R57  ValueDisplayed: 1.0k  [0603]  (hidden comment: CRCW06031K00JNEA)
R58  ValueDisplayed: 0  [0603]  (hidden comment: CRCW06030000Z0EA)
R59  ValueDisplayed: 0  [0603]  (hidden comment: CRCW06030000Z0EA)
R60  ValueDisplayed: 274k  [0603]  (hidden comment: CRCW0603274KFKEA)
R61  ValueDisplayed: 0  [0603]  (hidden comment: CRCW06030000Z0EA)
R62  ValueDisplayed: 274k  [0603]  (hidden comment: CRCW0603274KFKEA)
R63  ValueDisplayed: 31.6k  [0603]  (hidden comment: CRCW060331K6FKEA)
R64  value 300  [0603]  (hidden comment: CRCW0603300RJNEA)
R65  ValueDisplayed: 0  [0603]  (hidden comment: CRCW06030000Z0EA)
R66  ValueDisplayed: 27.4k  [0603]  (hidden comment: CRCW060327K4FKEA)
R67  ValueDisplayed: 0  [0603]  (hidden comment: CRCW06030000Z0EA)
R68  ValueDisplayed: 300  [0603]  (hidden comment: CRCW0603300RJNEA)
R70  value 0  [0805_HV]  (hidden comment: CRCW08050000Z0EA)
R71  ValueDisplayed: 0  [0603]  (hidden comment: RMCF0603ZT0R00)
R72  ValueDisplayed: 300  [0603]  (hidden comment: CRCW0603300RJNEA)
SH-J1  881545-2  [TE_881545-2]  (value not drawn)  (mechanical)
SH-J2  881545-2  [TE_881545-2]  (value not drawn)  (mechanical)
TP1  +5V  [Keystone5010]
TP2  Suggest using a net name here  [Mill-Max_0253-0-15-15-30-27-10-0]  (value not drawn)
TP3  (no value)  [Keystone5126]
TP4  Suggest using a net name here  [Mill-Max_0253-0-15-15-30-27-10-0]  (value not drawn)
TP5  (no value)  [Keystone5010]
TP6  Suggest using a net name here  [Mill-Max_0253-0-15-15-30-27-10-0]  (value not drawn)
TP7  Suggest using a net name here  [Mill-Max_0253-0-15-15-30-27-10-0]  (value not drawn)
TP8  Suggest using a net name here  [Mill-Max_0253-0-15-15-30-27-10-0]  (value not drawn)
U5  TPS22914YFP  [YFP0004ABAB]
U6  LP2992AILD-5.0/NOPB  [LDE06A]
U7  TPS65131RGET  [RGE0024B]
U8  TPS7A3901DSC  [DSC0010J]
U9  TPS7A6533QKVURQ1  [KVU0003A_N]
U11  SN74LV1T04DCKR  [DCK0005A_N]  (parts A,B of 2)

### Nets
+3.3V: C70.1 C71.1 D16.1(K) FB1.2 J5.34 TP6.1
+5V: C41.1 D12.1(K) R48.2 TP1.1 U6.6(OUT)
+5V_IN: C39.1 C40.1 C47.1 C56.1 C73.1 C74.1 C273.1 L1.1 R56.1 U5.A1(VOUT) U6.3(ON/~{OFF}) U6.4(IN) U7.5(INN) U7.6(INN) U7.8(ENP) U7.9(PSP) U7.10(ENN) U7.11(PSN) U9.1(VIN)
+12V: D11.1(K) J5.39 R58.2 TP7.1
+14V: J2.1 J11.1 R59.1 R65.1
-12V: D14.2(A) J5.40 R67.2 TP8.1
-14V: J4.1 J12.1 R61.1
AGND: C39.2 C40.2 C41.2 C42.2(-) C43.2 C44.2 C45.2 C46.2 C47.2 C48.2 C49.1 C51.1 C53.2 C54.2 C55.2 C56.2 C57.2 C58.2 C59.2 C60.2 C62.1 C63.2 C64.2 C66.2 C67.2 C68.1 C69.2 C72.2 C73.2 C74.2 C272.2 C273.2 D11.2(A) D12.2(A) D13.2(K) D14.1(K) D17.2(K) J3.2 J5.35 J5.36 J5.37 J5.38 J11.2 J12.2 L2.2 R50.2 R63.1 R70.1 TP3.1 U5.B1(GND) U6.2(GND) U6.7(DAP) U7.2(PGND) U7.3(PGND) U7.19(AGND) U7.25(PP) U8.4(GND) U8.11(PAD) U9.4(GND)
DGND: C70.2 C71.2 C75.2 D16.2(A) J5.9 J5.10 J5.19 J5.20 J5.29 J5.30 J5.31 J5.32 Q2.4(S) Q2.7(S) R70.2 U11.3(GND)
V_IN: C75.1 C272.1 J3.1 J3.1A R68.2 U5.A2(VIN) U11.5(VCC)
CS1: J5.3 ; off-sheet CS1
CS2: J5.4 ; off-sheet CS2
CS3: J5.13 ; off-sheet CS3
CS4: J5.14 ; off-sheet CS4
CS5: J5.23 ; off-sheet CS5
CS6: J5.24 ; off-sheet CS6
OE: J5.33 R71.1 ; off-sheet OE
ON: Q2.1(D) Q2.2(D) Q2.5(D) Q2.6(D) Q2.8(D) R68.1 U5.B2(ON) ; off-sheet ON
SCLK_1: J5.5 ; off-sheet SCLK_1
SCLK_2: J5.6 ; off-sheet SCLK_2
SCLK_3: J5.15 ; off-sheet SCLK_3
SCLK_4: J5.16 ; off-sheet SCLK_4
SCLK_5: J5.25 ; off-sheet SCLK_5
SCLK_6: J5.26 ; off-sheet SCLK_6
SDI_1: J5.1 ; off-sheet SDI_1
SDI_2: J5.2 ; off-sheet SDI_2
SDI_3: J5.11 ; off-sheet SDI_3
SDI_4: J5.12 ; off-sheet SDI_4
SDI_5: J5.21 ; off-sheet SDI_5
SDI_6: J5.22 ; off-sheet SDI_6
SDO_1: J5.7 ; off-sheet SDO_1
SDO_2: J5.8 ; off-sheet SDO_2
SDO_3: J5.17 ; off-sheet SDO_3
SDO_4: J5.18 ; off-sheet SDO_4
SDO_5: J5.27 ; off-sheet SDO_5
SDO_6: J5.28 ; off-sheet SDO_6
NetC42_1: C42.1(+) C43.1 C44.1 C45.1 C46.1 J2.2 R46.2 R47.2 R49.2 TP2.1
NetC48_1: C48.1 U6.1(CBYP)
NetC49_2: C49.2 R54.1 U7.17(VREF)
NetC50_1: C50.1 R47.1
NetC50_2: C50.2 R49.1 R50.1 U7.22(FBP)
NetC51_2: C51.2 R51.2
NetC52_1: C52.1 R55.1
NetC52_2: C52.2 R52.1 R54.2 U7.16(FBN)
NetC53_1: C53.1 C54.1 C57.1 C58.1 C59.1 D15.2(A) J4.2 R53.2 TP4.1 U7.15(VNEG)
NetC55_1: C55.1 R56.2 U7.4(VIN)
NetC60_1: C60.1 R57.2
NetC61_1: C61.1 C64.1 R58.1 R60.2 U8.10(OUTP)
NetC61_2: C61.2 R60.1 R63.2 U8.9(FBP)
NetC62_2: C62.2 C63.1 R59.2 U8.1(INP)
NetC65_1: C65.1 C66.1 R62.2 R67.1 U8.6(OUTN)
NetC65_2: C65.2 R62.1 R66.2 U8.7(FBN)
NetC67_1: C67.1 U8.3(NR/SS)
NetC68_2: C68.2 C69.1 R61.2 U8.5(INN)
NetC72_1: C72.1 FB1.1 R64.2 U9.3(VOUT)
NetD10_1: D10.1(K) R46.1 U7.23(VPOS)
NetD10_2: D10.2(A) L1.2 U7.1(INP) U7.24(INP)
NetD13_1: D13.1(A) R48.1
NetD15_1: D15.1(K) L2.1 U7.13(OUTN) U7.14(OUTN)
NetD17_1: D17.1(A) R64.1
NetQ2_3: Q2.3(G) R72.1
NetR51_1: R51.1 U7.18(CN)
NetR52_2: R52.2 R53.1 R55.2
NetR57_1: R57.1 U7.21(CP)
NetR65_2: R65.2 U8.2(EN)
NetR66_1: R66.1 U8.8(BUF)
NetR71_2: R71.2 U11.2(A)
NetR72_2: R72.2 U11.4(Y)
NetTP5_1: TP5.1 U7.7(BSW)

Not connected (* = marked no-connect by the designer): J3 3*; U6 5(NC)*; U7 12(NC) 20(NC); U11 1(NC)*

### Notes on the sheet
- INPUT VOLTAGE: +5.5V

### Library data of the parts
C39 = GRM31CR71E106KA12L: CAP, CERM, 10uF, 25V, +/-10%, X7R, 1206; Manufacturer: Wurth; Polarized: N; CompType: Capacitor; U/M: EA; Cap_F: 0.00001; Tolerance_%: 10; Value1: Unknown; VDC_V: 25; TaMin_C: -55; TaMax_C: 125; Cap_Case: 2220
C40 = 06033C104JAT2A: CAP, CERM, 0.1uF, 25V, +/-5%, X7R, 0603; Manufacturer: AVX; Polarized: N; CompType: Capacitor; U/M: EA; Cap_F: 0.0000001; Tolerance_%: 5; ESR_Ohm: 0.05; Value1: 0.05 ohm; VDC_V: 25; TaMin_C: -55; TaMax_C: 125
C41 C43-C45 C47 C54 C56-C59 = C3216X7R1E475M: CAP, CERM, 4.7 µF, 25 V, +/- 20%, X7R, 1206; Manufacturer: TDK; Polarized: N; CompType: Capacitor; Value: 4.7uF; U/M: EA; Cap_F: 0.0000047; Tolerance_%: 20; ESR_ohm: 0.0063; Value1: 0.0063 ohm; VDC_V: 25; Value2: 25V; TaMin_C: -55; TaMax_C: 125
C42 = 293D475X9025C2TE3: CAP, TA, 4.7 µF, 25 V, +/- 10%, 2 ohm, SMD; Manufacturer: Vishay-Sprague; Polarized: Y; CompType: Capacitor; Value: 4.7uF; U/M: EA; Cap_F: 0.0000047; Tolerance_%: 10; Value1: 2 ohm; VDC_V: 25; Value2: 25V; ESR_ohm: 2; IRMS_A: 0.24; TaMin_C: -55; TaMax_C: 125; Cap_Case: C
C46 C51 C60 C67 = GRM188R70J103KA01D: CAP, CERM, 0.01 µF, 6.3 V, +/- 10%, X7R, 0603; Manufacturer: MuRata; Polarized: N; CompType: Capacitor; Value: 0.01uF; U/M: EA; Cap_F: 0.00000001; Tolerance_%: 10; Value1: Unknown; VDC_V: 6.3; Value2: 6.3V; TaMin_C: -55; TaMax_C: 125
C48 = C1608X7R1H103K080AA: as C242 on sheet Page6
C49 = C0603C224K4RACTU: CAP, CERM, 0.22 µF, 6.3 V, +/- 10%, X7R, 0603; Manufacturer: Kemet; Polarized: N; CompType: Capacitor; Value: 0.22uF; U/M: EA; Cap_F: 0.00000022; Tolerance_%: 10; Value1: Unknown; VDC_V: 16; Value2: 16V; TaMin_C: -55; TaMax_C: 125
C50 C52 = C0603C100J5GACTU: CAP, CERM, 10 pF, 50 V, +/- 5%, C0G/NP0, 0603; Manufacturer: Kemet; Polarized: N; CompType: Capacitor; Value: 10pF; U/M: EA; Cap_F: 0.00000000001; Tolerance_%: 5; Value1: Unknown; VDC_V: 50; Value2: 50V; TaMin_C: -55; TaMax_C: 125
C53 C61 C65 = 06033C104JAT2A: CAP, CERM, 0.1 µF, 25 V,+/- 5%, X7R, 0603; Manufacturer: AVX; Polarized: N; CompType: Capacitor; Value: 0.1uF; U/M: EA; Cap_F: 0.0000001; Tolerance_%: 5; ESR_ohm: 0.05; Value1: 0.05 ohm; VDC_V: 25; Value2: 25V; TaMin_C: -55; TaMax_C: 125; SizeArea_mm2: 1.28; SizeAreaWB_mm2: 4.68; SizeX_mm: 1.6; SizeY_mm: 0.8; SizeZ_mm: 1; AEC Category: Q200; Green_Lifecycle: Active; Green_REACh: Passed
C55 C63 C69 = GRM188R61E105KA12D: CAP, CERM, 1 µF, 25 V, +/- 10%, X5R, 0603; Manufacturer: MuRata; Polarized: N; CompType: Capacitor; Value: 1uF; U/M: EA; Cap_F: 0.000001; Tolerance_%: 10; Value1: Unknown; VDC_V: 25; Value2: 25V; TaMin_C: -55; TaMax_C: 85
C62 C68 = GMK325AB7106MM-T: CAP, CERM, 10uF, 35V, +/-20%, X7R, 1210; Manufacturer: Taiyo Yuden; Polarized: N; CompType: Capacitor; U/M: EA; Cap_F: 0.00001; Tolerance_%: 20; Value1: Unknown; VDC_V: 35; TaMin_C: -55; TaMax_C: 125
C64 C66 = C0805C225K8RACTU: CAP, CERM, 2.2uF, 10V, +/-10%, X7R, 0805; Manufacturer: Kemet; Polarized: N; CompType: Capacitor; U/M: EA; Cap_F: 0.0000022; Tolerance_%: 10; ESR_Ohm: 0.008; Value1: 0.008 ohm; IRMS_A: 15.55; TaMin_C: -55; TaMax_C: 125; Cap_Case: 0805
C70 = C2012X5R1H475K125AB: CAP, CERM, 4.7uF, 50V, +/-10%, X5R, 0805; Manufacturer: TDK; Polarized: N; CompType: Capacitor; U/M: EA; Cap_F: 0.0000047; Tolerance_%: 10; Value1: Unknown; VDC_V: 50; TaMin_C: -55; TaMax_C: 85; Cap_Case: 0805
C71 C74 = C0603C104K5RACTU: CAP, CERM, 0.1uF, 50V, +/-10%, X7R, 0603; Manufacturer: Kemet; Polarized: N; CompType: Capacitor; U/M: EA; Cap_F: 0.0000001; Tolerance_%: 10; Value1: Unknown; VDC_V: 50; TaMin_C: -55; TaMax_C: 125
C72 C73 = GRM188R61H105KAALD: CAP, CERM, 1uF, 50V, +/-10%, X5R, 0603; Manufacturer: TDK; Polarized: N; CompType: Capacitor; U/M: EA; Cap_F: 0.000001; Tolerance_%: 10; Value1: Unknown; VDC_V: 50; TaMin_C: -55; TaMax_C: 85
C75 C273 = GRM188R71C104KA01D: as C261 on sheet Page6
C272 = C1608X7R1C105K080AC: as C253 on sheet Page6
D10 D15 = MBRM120ET1G: Diode, Schottky, 20 V, 1 A, POWERMITE; Manufacturer: ON Semiconductor; U/M: EA; Vf_V: 0.53; Value: 20V; Value1: 1A; Value2: 0.53V; Io_A: 1; Vr_V: 20
D11 D14 = DZ2W15000L: Diode, Zener, 15V, 1W, SOD-123; Manufacturer: Panasonic
D12 = MMSZ5232B-7-F: Diode, Zener, 5.6 V, 500 mW, SOD-123; Manufacturer: Diodes Inc.; SymbolCreator: a0412235; U/M: EA; Power_W: 0.5; Vz_V: 5.6; Value1: 0.5W; RJA_CperW: 350; AEC Category: Q101
D13 D17 = LG L29K-G2J1-24-Z: LED, Green, SMD; Manufacturer: OSRAM; Vf_V: 1.7; Value2: 1.7V; Io_A: 0.002; Tjmax_C: 110; Value1: W; U/M: EA
D16 = MMSZ4685-V: Diode, Zener, 3.6V, 500mW, SOD-123; Manufacturer: On semiconductor; U/M: EA; Power_W: 0.5; Vz_V: 3.6; Value1: 0.5W; RJA_CperW: 67
FB1 = MMZ1608B102CTA00: Ferrite Bead, 1000 ohm @ 100 MHz, 0.3 A, 0603; Manufacturer: TDK; Imax_A: 0.3; DCR_ohm: 0.6; Value1: 0.6 ohm; Value2: 0.3A; ZTyp@100MHz_Ohm: 1000
J2 J4 = TSW-102-07-G-S: Header, 100mil, 2x1, Gold, TH; Manufacturer: TE Connectivity; SymbolCreator: a0412235; U/M: EA
J3 = PJ-002AH-SMT-TR: Power Jack, SMT; Manufacturer: CUI Inc.; SymbolCreator: a0411947; Green_Lifecycle: Not Set; Green_REACh: Incomplete
J5 = ZSS-120-01-L-D-529: Elevated Header, 100 mil, 20x2, TH; Manufacturer: Samtec; SymbolCreator: a0412235; CompType: Connector
J11 J12 = PEC02SAAN: Header, 100mil, 2x1, Tin, TH; Manufacturer: Sullins Connector Solutions; SymbolCreator: a0412235; Pitch_mm: 2.54; Gender: Male; Shrouded: N; Row_Count: 1; Current_A: 3; Voltage_V: 1800; Cert_UL: Y
L1 L2 = VLF504012MT-4R7M: Inductor, Shielded, Ferrite, 4.7 µH, 1.83 A, 0.1 ohm, SMD; Manufacturer: TDK; Value: 4.7uH; Ind_H: 4.7E-6; Imax_A: 1.83; Irms: 1.83A @ 40C rise; Isat: 1.94A @ 30% inductance drop; DCR_ohm: 0.1; Value1: 0.1 ohm; Value2: 1.83A; SizeAreaWB_mm2: 45.26; SizeArea_mm2: 22.26; SizeX_mm: 4.2; SizeY_mm: 5.3; SizeZ_mm: 1.2; AEC Category: Q200; Green_Lifecycle: NRND; Green_REACh: Passed
Q2 = CSD17571Q2: as Q7 on sheet Page6
R46 = CRCW12060000Z0EA: RES, 0 ohm, 5%, 0.25W, 1206; Manufacturer: Vishay-Dale; CompType: Resistor; Value_Code: 0000; Tolerance_%: 5; Power_W: 0.25; VDC_V: 200; TempCo: 200 ppm/C; EIA_Code: E24; U/M: EA
R47 = CRCW06030000Z0EA: RES, 0, 5%, 0.1 W, 0603; Manufacturer: Vishay-Dale; CompType: Resistor; Value: 0; Value_Code: 0000; Tolerance_%: 5; Power_W: 0.1; Value2: 0.1W; VDC_V: 75; TempCo: 200 ppm/C; SizeArea_mm2: 1.28; SizeX_mm: 1.6; SizeY_mm: 0.8; SizeZ_mm: 1; EIA_Code: E24; U/M: EA; AEC Category: Q200; Green_Lifecycle: Active; Green_REACh: Passed
R48 = RC0603FR-07820RL: RES, 820, 1%, 0.1 W, 0603; Manufacturer: Yageo America; CompType: Resistor; Value: 820; Value_Code: 820R; Tolerance_%: 1; Power_W: 0.1; Value2: 0.1W; VDC_V: 150; TempCo: 200 ppm/C; SizeArea_mm2: 1.28; SizeX_mm: 1.6; SizeY_mm: 0.8; U/M: EA; AEC Category: Q200
R49 = CRCW0603576KFKEA: RES, 576 k, 1%, 0.1 W, 0603; Manufacturer: Vishay-Dale; CompType: Resistor; Value: 576k; Res_ohm: 576000; Tolerance_%: 1; Power_W: 0.1; Value2: 0.1W; VDC_V: 75; TempCo: 100 ppm/C; SizeArea_mm2: 1.28; SizeX_mm: 1.6; SizeY_mm: 0.8; EIA_Code: E96; U/M: EA; AEC Category: Q200
R50 = RG1608P-4992-B-T5: RES, 49.9 k, 0.1%, 0.1 W, 0603; Manufacturer: Susumu Co Ltd; CompType: Resistor; Value: 49.9k; Res_ohm: 49900; Value_Code: 49k9; Tolerance_%: 0.1; Value2: 0.1W; VDC_V: 75; TempCo: 25 ppm/C; SizeArea_mm2: 1.28; SizeX_mm: 1.6; SizeY_mm: 0.8; SizeZ_mm: 1; EIA_Code: E192; U/M: EA; AEC Category: Q200; Green_Lifecycle: Active; Green_REACh: Passed
R51 R53 R58 R59 R61 R65 R67 = CRCW06030000Z0EA: as R257-R264 on sheet Page6
R52 = RC0603FR-07620KL: RES SMD 620K OHM 1% 1/10W 0603; Manufacturer: Vishay-Dale; CompType: Resistor; Res_ohm: 620000; Tolerance_%: 1; Power_W: 0.1; Value2: 0.1W; VDC_V: 150; TempCo: 200 ppm/C; U/M: EA
R54 R55 = RG1608P-4992-B-T5: RES, 49.9 k, 0.1%, 0.1 W, 0603; Manufacturer: Susumu Co Ltd; CompType: Resistor; Value: 49.9k; Res_ohm: 49900; Value_Code: 49k9; Tolerance_%: 0.1; Value2: 0.1W; VDC_V: 75; TempCo: 25 ppm/C; EIA_Code: E192; U/M: EA
R56 = RT0603DRE071RL: RES SMD 1 OHM 5% 1/10W 0603; Manufacturer: Bourns inc; CompType: Resistor; Value: 1.00; Res_ohm: 1; Value_Code: 1R00; Tolerance_%: 0.5; Value1: 0.5%; Power_W: 0.1; Value2: 0.1W; VDC_V: 75; TempCo: 50 ppm/C; EIA_Code: E192; U/M: EA
R57 = CRCW06031K00JNEA: RES, 1.0 k, 5%, 0.1 W, 0603; Manufacturer: Vishay-Dale; CompType: Resistor; Value: 1.0k; Res_ohm: 1000; Value_Code: 1k00; Tolerance_%: 5; Power_W: 0.1; Value2: 0.1W; VDC_V: 75; TempCo: 200 ppm/C; EIA_Code: E24; U/M: EA
R60 R62 = CRCW0603274KFKEA: RES, 274 k, 1%, 0.1 W, 0603; Manufacturer: Vishay-Dale; CompType: Resistor; Value: 274k; Res_ohm: 274000; Tolerance_%: 1; Power_W: 0.1; Value2: 0.1W; VDC_V: 75; TempCo: 100 ppm/C; SizeArea_mm2: 1.28; SizeX_mm: 1.6; SizeY_mm: 0.8; EIA_Code: E96; U/M: EA; AEC Category: Q200; Green_Lifecycle: Active; Green_REACh: Passed
R63 = CRCW060331K6FKEA: RES, 31.6 k, 1%, 0.1 W, 0603; Manufacturer: Vishay-Dale; CompType: Resistor; Value: 31.6k; Res_ohm: 31600; Value_Code: 31k6; Tolerance_%: 1; Power_W: 0.1; Value2: 0.1W; VDC_V: 75; TempCo: 100 ppm/C; SizeArea_mm2: 1.28; SizeX_mm: 1.6; SizeY_mm: 0.8; EIA_Code: E96; U/M: EA; AEC Category: Q200; Green_Lifecycle: Active; Green_REACh: Passed
R64 = CRCW0603300RJNEA: RES, 300 ohm, 5%, 0.1W, 0603; Manufacturer: Vishay-Dale; CompType: Resistor; Value_Code: 300R; Tolerance_%: 5; Power_W: 0.1; VDC_V: 75; TempCo: 200 ppm/C; EIA_Code: E24; U/M: EA
R66 = CRCW060327K4FKEA: RES, 27.4 k, 1%, 0.1 W, 0603; Manufacturer: Vishay-Dale; CompType: Resistor; Value: 27.4k; Res_ohm: 27400; Value_Code: 27k4; Tolerance_%: 1; Power_W: 0.1; Value2: 0.1W; VDC_V: 75; TempCo: 100 ppm/C; SizeArea_mm2: 1.28; SizeX_mm: 1.6; SizeY_mm: 0.8; EIA_Code: E96; U/M: EA; AEC Category: Q200; Green_Lifecycle: Active; Green_REACh: Passed
R68 R72 = CRCW0603300RJNEA: as R291 on sheet Page6
R70 = CRCW0805330KJNEA: RES, 0 ohm, 5%, 0.125W, 0805; Manufacturer: Vishay-Dale; CompType: Resistor; Tolerance_%: 5; Power_W: 0.125; VDC_V: 150; TempCo: 200 ppm/C; EIA_Code: E24; U/M: EA
R71 = RMCF0603ZT0R00: as R294 on sheet Page6
SH-J1 SH-J2 = 881545-2: Shunt, 100mil, Gold plated, Black; Manufacturer: TE Connectivity
TP1 TP5 = 5010: Test Point, Multipurpose, Red, TH; Manufacturer: Keystone; CompType: Test Point Loop; U/M: EA
TP2 TP4 TP6-TP8 = 0253-0-15-15-30-27-10-0: Pin Receptacle, Dia 0.015-0.025", Length 0.173", Gold, TH; Manufacturer: Mill-Max; Gender: Female
TP3 = 5126: Test Point, Multipurpose, Green, TH; Manufacturer: Keystone; SymbolCreator: a0412235; CompType: Test Point Loop; U/M: EA
U5 = TPS22914YFP: Single Channel Ultra-Low Resistnace Load Switch, YFP0004ABAB (DSBGA-4); Manufacturer: Texas Instruments; SymbolCreator: a0799628; SizeArea_mm2: 0.602176; SizeAreaWB_mm2: 3.154176; SizeX_mm: 0.776; SizeZ_mm: 0.5; CompType: IC; U/M: EA
U6 = LP2992AILD-5.0/NOPB: Micropower 250 mA Low-Noise Ultra Low-Dropout Regulator, 6-pin LLP, Pb-Free; Manufacturer: Texas Instruments; PackageTopMarking: ZXYTT*L015A; PowerWise: N; CompType: LDO IC
U7 = TPS65131RGET: Postive and Negative Output DC-DC Converter, 2.7 to 5.5 V, -40 to 85 degC, 24-pin QFN (RGE24), Green (RoHS & no Sb/Br); Manufacturer: Texas Instruments; Alternate Manufacturer: None; Alternate PartNumber: Equivalent; Iq(Typ)(mA): 0.5; Rating: Catalog; SubFamily: LCD/OLED Display Bias Solutions; Switching Frequency(Typ)(kHz): 1400; Synchronous Rectification: TRUE; Topology: Boost, Inverting Buck/Boost; Vin(Max)(V): 5.5; Vin(Min)(V): 2.7
U8 = TPS7A3901DSC: Wide-VIN (±33 V), 150-mA, Spilt-Rail Output, Positive and Negative LDO Voltage Regulator with Startup Tracking, DSC0010J; Manufacturer: Texas Instruments; SymbolCreator: Altium; SizeArea_mm2: 9; SizeAreaWB_mm2: 16; SizeX_mm: 3; SizeZ_mm: 0.8; CompType: IC; U/M: EA
U9 = TPS7A6533QKVURQ1: Automotive 300-mA 40-V Low-Dropout Regulator With Ultra-Low Quiescent Current, KVU0003A (TO-252-3); Manufacturer: Texas Instruments; SymbolCreator: a0411947; SizeArea_mm2: 66.66; SizeAreaWB_mm2: 104.06; SizeX_mm: 10.1; SizeY_mm: 6.6; SizeZ_mm: 2.52; U/M: EA
U11 = SN74LV1T04DCKR: Single Power Supply INVERTER Gate logic level shifter, DCK0005A, LARGE T&R; Manufacturer: Texas Instruments; Alternate PartNumber: Equivalent; VCC(Min)(V): 1.6; VCC(Max)(V): 5.5; Output Type: CMOS; Logic: Inverting; ICC @ Nom Voltage(Max)(mA): 0.01; Input Type: TTL; Bits(#): 1; F @ Nom Voltage(Max)(Mhz): 50; Rating: Catalog; Technology Family: LV1T; Voltage(Nom)(V): 1.8,2.5,3.3,5.5; Schmitt Trigger: No; Output Drive (IOL/IOH)(Max)(mA): 8/-8; Sub-Family: Inverting Buffer/Driver; Special Features: 1.8V to 3.3V Up Translation,3.3V to 1.8V Down Translation,5V Input Tolerant; 3-State Output: Yes; tpd @ Nom Voltage(Max)(ns): 13,7.5,5.5,7.0

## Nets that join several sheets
+3.3V: Page1 (11 pins), Page2 (11 pins), Page3 (11 pins), Page4 (11 pins), Page5 (11 pins), Page6 (11 pins), Paget2 (6 pins)
+5V: Page1 (C5.1 C6.1 C7.1 R298.2), Page2 (C80.1 C81.1 C82.1 R300.2), Page3 (C118.1 C119.1 C120.1 R302.2), Page4 (C156.1 C157.1 C158.1 R304.2), Page5 (C194.1 C195.1 C196.1 R306.2), Page6 (C232.1 C233.1 C234.1 R308.2), Paget2 (5 pins)
+12V: Page1 (11 pins), Page2 (11 pins), Page3 (11 pins), Page4 (11 pins), Page5 (11 pins), Page6 (11 pins), Paget2 (D11.1 J5.39 R58.2 TP7.1)
-12V: Page1 (11 pins), Page2 (11 pins), Page3 (11 pins), Page4 (11 pins), Page5 (11 pins), Page6 (11 pins), Paget2 (D14.2 J5.40 R67.2 TP8.1)
AGND: Page1 (36 pins), Page2 (36 pins), Page3 (36 pins), Page4 (36 pins), Page5 (36 pins), Page6 (36 pins), Paget2 (59 pins)
DGND: Page1 (11 pins), Page2 (11 pins), Page3 (11 pins), Page4 (11 pins), Page5 (11 pins), Page6 (11 pins), Paget2 (16 pins)
CS1: Page1 (R42.1 U3.38), Paget2 (J5.3)
CS2: Page2 (R114.1 U14.38), Paget2 (J5.4)
CS3: Page3 (R159.1 U18.38), Paget2 (J5.13)
CS4: Page4 (R204.1 U22.38), Paget2 (J5.14)
CS5: Page5 (R249.1 U26.38), Paget2 (J5.23)
CS6: Page6 (R294.1 U30.38), Paget2 (J5.24)
SCLK_1: Page1 (U3.37), Paget2 (J5.5)
SCLK_2: Page2 (U14.37), Paget2 (J5.6)
SCLK_3: Page3 (U18.37), Paget2 (J5.15)
SCLK_4: Page4 (U22.37), Paget2 (J5.16)
SCLK_5: Page5 (U26.37), Paget2 (J5.25)
SCLK_6: Page6 (U30.37), Paget2 (J5.26)
SDI_1: Page1 (U3.1), Paget2 (J5.1)
SDI_2: Page2 (U14.1), Paget2 (J5.2)
SDI_3: Page3 (U18.1), Paget2 (J5.11)
SDI_4: Page4 (U22.1), Paget2 (J5.12)
SDI_5: Page5 (U26.1), Paget2 (J5.21)
SDI_6: Page6 (U30.1), Paget2 (J5.22)
SDO_1: Page1 (U10.4), Paget2 (J5.7)
SDO_2: Page2 (U32.4), Paget2 (J5.8)
SDO_3: Page3 (U33.4), Paget2 (J5.17)
SDO_4: Page4 (U34.4), Paget2 (J5.18)
SDO_5: Page5 (U35.4), Paget2 (J5.27)
SDO_6: Page6 (U36.4), Paget2 (J5.28)

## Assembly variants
001: not fitted FID1 FID2 FID3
